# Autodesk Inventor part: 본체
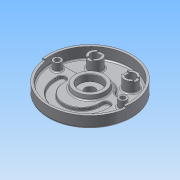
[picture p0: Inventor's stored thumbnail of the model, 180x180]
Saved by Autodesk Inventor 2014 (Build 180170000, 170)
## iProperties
Created: 2015-06
Part Number: 본체
Material: 알루미늄 6061
Document SubType Name: Modeling
Designer: Administrator
Density: 2.71 g/cm^3
Appearance: 알루미늄 - 평지
Mass: 1071 g
Surface Area: 1034.49 cm^2
Volume: 395.202 cm^3
Author: Administrator
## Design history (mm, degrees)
sketch "스케치1"
  geometry: C1 r 95 at (0, 0); 1 further point
  constraints: 1 centre point, 1 coincident
  dimensions: "d0" = 190 diameter of C1
extrude "돌출1" new body sketch "스케치1" distance "d1" = 32; taper "d2" = 0 deg
sketch "스케치2"
  geometry: L1 (-88.566, 16)-(-38.833, 16); L2 (38.833, 16)-(88.566, 16); C1 r 95 at (0, 0) reference; A1 r 90 centre (0, 0) between (88.566, 16) and (-88.566, 16); A2 r 42 centre (0, 0) between (38.833, 16) and (-38.833, 16)
  constraints: 4 end point, 4 point on circle, 2 centre point, 2 coincident, 2 collinear, 1 horizontal
  dimensions: "d3" = 180 diameter of A1; "d4" = 84 diameter of A2; "d5" = 16 distance from line of C1.centre L1
extrude "돌출2" cut sketch "스케치2" distance "d6" = 25; taper "d7" = 0 deg
fillet "모깎기1" dims "d8" = 10
sketch "스케치3"
  geometry: C1 r 15 at (-40, 52); C2 r 15 at (40, 52); A1 r 90 centre (0, 0) between (85.114, 29.25) and (-85.114, 29.25) reference
  constraints: 2 centre point, 1 equal radius, 1 horizontal alignment
  dimensions: "d9" = 80 distance of C2.centre C1.centre; "d10" = 40 horizontal distance of A1.centre C1.centre; "d11" = 52 vertical distance of A1.centre C2.centre; "d12" = 30 diameter of C1
extrude "돌출3" join sketch "스케치3" distance "d13" = 25; taper "d14" = 0 deg
node "작업 평면1"
sketch "스케치4"
  geometry: C1 r 15 at (0, 0) reference; C2 r 15 at (80, 0) reference; C3 r 10 at (0, 0); C4 r 10 at (80, 0); 1 further point
  constraints: 2 centre point, 2 coincident
  dimensions: "d16" = 20 diameter of C3; "d17" = 20 diameter of C4
extrude "돌출4" cut sketch "스케치4" stored distance "d18" = 25; taper "d19" = 0 deg
sketch "스케치5"
  geometry: L1 (-6, 13.748)-(-6, -13.748); L2 (6, 13.748)-(6, -13.748); L3 (66.252, 6)-(93.748, 6); L4 (66.252, -6)-(93.748, -6); C1 r 10 at (0, 0) reference; C2 r 10 at (80, 0) reference; A1 r 15 centre (0, 0) between (-6, 13.748) and (-6, -13.748) reference; A2 r 15 centre (80, 0) between (66.252, 6) and (93.748, 6) reference; 1 further point
  constraints: 8 end point, 8 point on circle, 2 parallel, 1 perpendicular, 1 vertical
  dimensions: "d20" = 12 distance between parallel lines of L2 L1; "d21" = 6 distance from line of A1.centre L1; "d22" = 12 distance between parallel lines of L4 L3; "d23" = 6 distance from line of L4 C2.centre
extrude "돌출5" cut sketch "스케치5" distance "d24" = 3; taper "d25" = 0 deg
sketch "스케치6"
  geometry: L1 (-45.033, 16)-(-75.657, 16) reference; L2 (75.657, 16)-(45.033, 16) reference; C1 r 95 at (0, 0) reference; A1 r 10 centre (-75.657, 26) between (-85.114, 29.25) and (-75.657, 16) reference; A2 r 90 centre (0, 0) between (85.114, 29.25) and (-85.114, 29.25) reference; A3 r 10 centre (75.657, 26) between (75.657, 16) and (85.114, 29.25) reference; A4 r 10 centre (45.033, 26) between (36.373, 21) and (45.033, 16) reference; A5 r 42 centre (0, 0) between (36.373, 21) and (-36.373, 21) reference; A6 r 10 centre (-45.033, 26) between (-45.033, 16) and (-36.373, 21) reference; 1 further point
  constraints: 1 coincident, 3 other
extrude "돌출6" cut sketch "스케치6" distance "d26" = 18; taper "d27" = 0 deg
sketch "스케치7"
  geometry: C1 r 35 at (0, 0); A1 r 42 centre (0, 0) between (36.373, 21) and (-36.373, 21) reference
  constraints: 1 centre point, 1 coincident
  dimensions: "d28" = 70 diameter of C1
extrude "돌출7" join sketch "스케치7" distance "d29" = 10; taper "d30" = -10 deg
sketch "스케치8"
  geometry: C1 r 95 at (0, 0) reference; C2 r 26 at (0, 0)
  constraints: 1 centre point, 1 coincident
  dimensions: "d31" = 52 diameter of C2
extrude "돌출8" join sketch "스케치8" distance "d32" = 12; taper "d33" = -15 deg
hole "구멍1" diameter "d36" = 23; stored, may be unused: countersink angle "d40" = 90 deg, drill point angle "d42" = 0 deg; dims "d34" = 10, "d35" = 10, "d37" = 6, "d38" = 50, "d39" = 15, "d41" = 8
sketch "스케치9"
  geometry: C1 r 35 at (0, 0) reference; C2 r 9 at (-74, 0); C3 r 9 at (74, 0)
  constraints: 2 centre point, 2 horizontal alignment, 1 equal radius
  dimensions: "d43" = 148 distance of C3.centre C2.centre; "d44" = 74 distance of C1.centre C2.centre; "d45" = 18 diameter of C2
extrude "돌출9" join sketch "스케치9" distance "d46" = 18; taper "d47" = 0 deg
sketch "스케치10"
  geometry: C1 r 26 at (0, 0) reference; C2 r 10 at (40, 52) reference; C3 r 10 at (-40, 52) reference; C4 r 95 at (0, 0) reference; C5 r 9 at (-74, 0) reference; C6 r 9 at (74, 0) reference; 2 further points
  constraints: 2 coincident
hole "구멍2" sketch "스케치10" at (-74, 0), (74, 0) diameter "d48" = 11; stored, may be unused: countersink angle "d52" = 90 deg, drill point angle "d54" = 0 deg; dims "d49" = 6, "d50" = 18, "d51" = 11, "d53" = 8
sketch "스케치11"
  geometry: L1 (-75.657, 16)-(-45.033, 16) reference; L2 (-59, -19)-(59, -19); L3 (-59, -19)-(-59, -14); L4 (-41, -19)-(-41, -14); L5 (41, -19)-(41, -14); L6 (59, -19)-(59, -14); C1 r 35 at (0, 0) reference; A1 r 41 centre (0, -19) between (-41, -19) and (41, -19); A2 r 59 centre (0, -19) between (-59, -19) and (59, -19); A3 r 9 centre (-50, -14) between (-41, -14) and (-59, -14); A4 r 9 centre (50, -14) between (59, -14) and (41, -14)
  constraints: 10 end point, 8 point on circle, 8 tangent, 7 parallel, 4 centre point, 2 point on line, 1 coincident, 1 perpendicular, 1 vertical alignment
  dimensions: "d57" = 19 distance of C1.centre A1.centre; "d59" = 59 radius of A2; "d60" = 41 radius of A1; "d61" = 5 distance of L2.start L3.end
extrude "돌출10" cut sketch "스케치11" distance "d62" = 7; taper "d63" = 0 deg
sketch "스케치12"
  geometry: C1 r 95 at (0, 0) reference; C2 r 68 at (0, 0)
  constraints: 1 centre point, 1 coincident, 1 other
  dimensions: "d66" = 136 diameter of C2
feature "엠보싱1" sketch "스케치12" dims "d67" = 0.5, "d68" = 0
sketch "스케치13"
  geometry: L1 (-95, 0)-(95, 0); L2 (0, 0)-(-94.075, -13.221); L3 (0, 0)-(94.075, -13.221); C1 r 90 at (0, 0) reference; A1 r 95 centre (0, 0) between (-95, 0) and (95, 0) reference; A2 r 95 centre (0, 0) between (-94.075, -13.221) and (94.075, -13.221); A3 r 90 centre (0, 0) between (-89.124, -12.526) and (89.124, -12.526)
  constraints: 8 point on circle, 6 end point, 2 centre point, 2 coincident, 2 concentric, 2 point on line, 1 horizontal
  dimensions: "d69" = 190 distance of L1.start L1.end; "d72" = 8 deg angle of L3 L1; "d73" = 8 deg angle of L2 L1
extrude "돌출11" cut sketch "스케치13" distance "d74" = 5; taper "d75" = 0 deg
fillet "모깎기2" dims "d76" = 3
chamfer "모따기1" distance "d77" = 1; stored, may be unused: second distance "d78" = 2, angle "d79" = 45 deg
fillet "모깎기3" dims "d80" = 1
chamfer "모따기2" distance "d81" = 1; stored, may be unused: second distance "d82" = 2, angle "d83" = 45 deg
fillet "모깎기4" dims "d84" = 5
fillet "모깎기5" dims "d85" = 3
fillet "모깎기6" dims "d86" = 0.3
fillet "모깎기7" dims "d87" = 3
fillet "모깎기8" dims "d88" = 3
fillet "모깎기9" dims "d89" = 3
fillet "모깎기10" dims "d90" = 3
node "솔리드1"
node "투영된 루프1"
node "투영된 루프2"
node "투영된 루프3"
node "투영된 루프4"
other parameters: "d15" = 0, "d55" = 59, "d56" = 41
